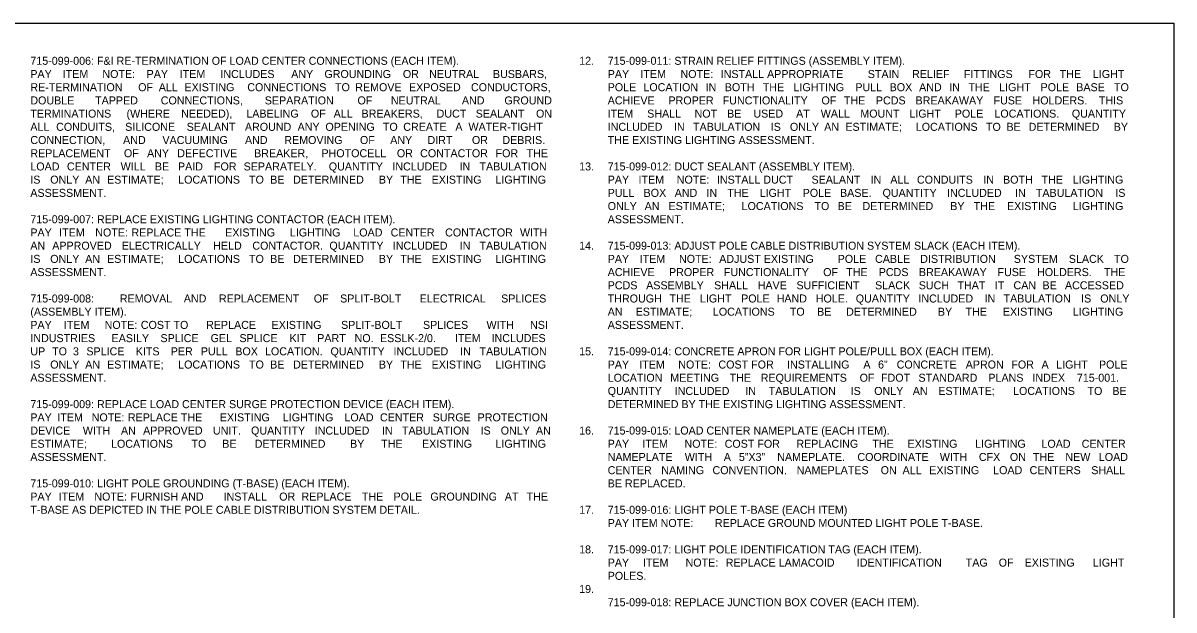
# Model space of a CAD drawing. Extents: x -55 to 2471539, y -90 to 3608906.
# Drawn here: x 543 to 1540, y 452 to 960 of the extents above; entities that cross this region are included whole.
import ezdxf

# ---------------------------------------------------------------- set-up
doc = ezdxf.new("R2010")
doc.units = 0
doc.layers.add('NonPlottingEle_dp', color=7, linetype='Continuous')
doc.layers.add('TextNotes', color=7, linetype='Continuous')

msp = doc.modelspace()

# ---------------------------------------------------------------- linework, layer by layer
at = {"layer": 'NonPlottingEle_dp'}
msp.add_lwpolyline([(0, 0), (0, 960), (1540, 960), (1540, 0)], dxfattribs=at)

# ---------------------------------------------------------------- texts
at = {"layer": 'TextNotes'}
for s, p in [('715-099-006: F&I RE-TERMINATION OF LOAD CENTER CONNECTIONS (EACH ITEM).', (549.7, 923.83)), ('12.', (1024.92, 923.83)), ('715-099-011: STRAIN RELIEF FITTINGS (ASSEMBLY ITEM).', (1049.65, 923.83)), ('PAY ', (549.7, 912.39)), ('ITEM ', (577.74, 912.39)), ('NOTE: ', (612.1, 912.39)), ('PAY ', (650.39, 912.39)), ('ITEM ', (679.08, 912.39)), ('INCLUDES ', (714.25, 912.39)), ('ANY ', (775.58, 912.39)), ('GROUNDING ', (804.34, 912.39)), ('OR ', (872.29, 912.39)), ('NEUTRAL ', (895.07, 912.39)), ('BUSBARS, ', (950.28, 912.39)), ('PAY ', (1049.65, 912.39)), ('ITEM ', (1077.96, 912.39)), ('NOTE:', (1112.68, 912.39)), (' INSTALL APPROPRIATE ', (1144.9, 912.39)), ('STAIN ', (1274.84, 912.39)), ('RELIEF ', (1313.22, 912.39)), ('FITTINGS ', (1358.13, 912.39)), ('FOR ', (1413.95, 912.39)), ('THE ', (1441.06, 912.39)), ('LIGHT ', (1469.78, 912.39)), ('RE-TERMINATION ', (549.7, 900.96)), ('OF ', (643.08, 900.96)), ('ALL ', (660.93, 900.96)), ('EXISTING ', (683.15, 900.96)), ('CONNECTIONS ', (737.56, 900.96)), ('TO ', (813.52, 900.96)), ('REMOVE ', (831.03, 900.96)), ('EXPOSED ', (877.57, 900.96)), ('CONDUCTORS, ', (931.26, 900.96)), ('POLE ', (1049.65, 900.96)), ('LOCATION ', (1080.56, 900.96)), ('IN ', (1134.43, 900.96)), ('BOTH ', (1151.04, 900.96)), ('THE ', (1183.91, 900.96)), ('LIGHTING ', (1210.53, 900.96)), ('PULL ', (1264.1, 900.96)), ('BOX ', (1293.78, 900.96)), ('AND ', (1319.3, 900.96)), ('IN ', (1345.38, 900.96)), ('THE ', (1361.99, 900.96)), ('LIGHT ', (1388.61, 900.96)), ('POLE ', (1424.48, 900.96)), ('BASE ', (1455.39, 900.96)), ('TO ', (1488.08, 900.96)), ('DOUBLE ', (549.7, 889.52)), ('TAPPED ', (605.77, 889.52)), ('CONNECTIONS, ', (662.65, 889.52)), ('SEPARATION ', (752.7, 889.52)), ('OF ', (833, 889.52)), ('NEUTRAL ', (861.91, 889.52)), ('AND ', (923.39, 889.52)), ('GROUND ', (960.17, 889.52)), ('ACHIEVE ', (1049.65, 889.52)), ('PROPER ', (1102.26, 889.52)), ('FUNCTIONALITY ', (1149.23, 889.52)), ('OF ', (1234.77, 889.52)), ('THE ', (1254.12, 889.52)), ('PCDS ', (1281.88, 889.52)), ('BREAKAWAY ', (1316.19, 889.52)), ('FUSE ', (1383.74, 889.52)), ('HOLDERS. ', (1417.5, 889.52)), ('THIS ', (1474.9, 889.52)), ('TERMINATIONS ', (549.7, 878.09)), ('(WHERE ', (633, 878.09)), ('NEEDED), ', (680.31, 878.09)), ('LABELING ', (736.72, 878.09)), ('OF ', (792.62, 878.09)), ('ALL ', (812.36, 878.09)), ('BREAKERS, ', (836.49, 878.09)), ('DUCT ', (901.5, 878.09)), ('SEALANT ', (935.34, 878.09)), ('ON ', (987.58, 878.09)), ('ITEM ', (1049.65, 878.09)), ('SHALL ', (1083.84, 878.09)), ('NOT ', (1124.85, 878.09)), ('BE ', (1153.02, 878.09)), ('USED ', (1175.78, 878.09)), ('AT ', (1212.78, 878.09)), ('WALL ', (1234.12, 878.09)), ('MOUNT ', (1268.41, 878.09)), ('LIGHT ', (1310.87, 878.09)), ('POLE ', (1350.18, 878.09)), ('LOCATIONS. ', (1384.52, 878.09)), ('QUANTITY ', (1451.55, 878.09)), ('ALL ', (549.7, 866.65)), ('CONDUITS, ', (572.05, 866.65)), ('SILICONE ', (631.83, 866.65)), ('SEALANT ', (685.05, 866.65)), ('AROUND ', (735.51, 866.65)), ('ANY ', (781.11, 866.65)), ('OPENING ', (805.22, 866.65)), ('TO ', (854.97, 866.65)), ('CREATE ', (872.61, 866.65)), ('A ', (917.72, 866.65)), ('WATER-TIGHT ', (929.09, 866.65)), ('INCLUDED ', (1049.65, 866.65)), ('IN ', (1107.05, 866.65)), ('TABULATION ', (1123.54, 866.65)), ('IS ', (1190.8, 866.65)), ('ONLY ', (1207.43, 866.65)), ('AN ', (1237.1, 866.65)), ('ESTIMATE; ', (1255.46, 866.65)), ('LOCATIONS ', (1316.43, 866.65)), ('TO ', (1377.19, 866.65)), ('BE ', (1394.94, 866.65)), ('DETERMINED ', (1414.15, 866.65)), ('BY ', (1487.82, 866.65)), ('CONNECTION, ', (549.7, 855.22)), ('AND ', (630.03, 855.22)), ('VACUUMING ', (664.09, 855.22)), ('AND ', (735.55, 855.22)), ('REMOVING ', (769.61, 855.22)), ('OF ', (835.13, 855.22)), ('ANY ', (861.32, 855.22)), ('DIRT ', (893.64, 855.22)), ('OR ', (932.08, 855.22)), ('DEBRIS. ', (958.43, 855.22)), ('THE EXISTING LIGHTING ASSESSMENT.', (1049.65, 855.22)), ('REPLACEMENT ', (549.7, 843.78)), ('OF ', (630.73, 843.78)), ('ANY ', (650.75, 843.78)), ('DEFECTIVE ', (676.9, 843.78)), ('BREAKER, ', (743.47, 843.78)), ('PHOTOCELL ', (801.75, 843.78)), ('OR ', (867.07, 843.78)), ('CONTACTOR ', (887.24, 843.78)), ('FOR ', (952.56, 843.78)), ('THE ', (979.39, 843.78)), ('LOAD ', (549.7, 832.35)), ('CENTER ', (581.37, 832.35)), ('WILL ', (627.9, 832.35)), ('BE ', (657.55, 832.35)), ('PAID ', (677.54, 832.35)), ('FOR ', (708.69, 832.35)), ('SEPARATELY. ', (734.37, 832.35)), ('QUANTITY ', (808.13, 832.35)), ('INCLUDED ', (863.18, 832.35)), ('IN ', (921.36, 832.35)), ('TABULATION ', (938.63, 832.35)), ('13.', (1024.92, 832.35)), ('715-099-012: DUCT SEALANT (ASSEMBLY ITEM).', (1049.65, 832.35)), ('IS ', (549.7, 820.92)), ('ONLY ', (566.92, 820.92)), ('AN ', (597.19, 820.92)), ('ESTIMATE; ', (616.14, 820.92)), ('LOCATIONS ', (677.71, 820.92)), ('TO ', (739.06, 820.92)), ('BE ', (757.41, 820.92)), ('DETERMINED ', (777.21, 820.92)), ('BY ', (851.47, 820.92)), ('THE ', (870.08, 820.92)), ('EXISTING ', (897.18, 820.92)), ('LIGHTING ', (952.43, 820.92)), ('PAY ', (1049.65, 820.92)), ('ITEM ', (1076.33, 820.92)), ('NOTE:', (1109.42, 820.92)), (' INSTALL DUCT ', (1141.64, 820.92)), ('SEALANT ', (1226.14, 820.92)), ('IN ', (1277.3, 820.92)), ('ALL ', (1294.38, 820.92)), ('CONDUITS ', (1317.44, 820.92)), ('IN ', (1374.88, 820.92)), ('BOTH ', (1391.96, 820.92)), ('THE ', (1425.29, 820.92)), ('LIGHTING ', (1452.38, 820.92)), ('ASSESSMENT.', (549.7, 809.48)), ('PULL ', (1049.65, 809.48)), ('BOX ', (1080.74, 809.48)), ('AND ', (1107.67, 809.48)), ('IN ', (1135.17, 809.48)), ('THE ', (1153.18, 809.48)), ('LIGHT ', (1181.21, 809.48)), ('POLE ', (1218.5, 809.48)), ('BASE. ', (1250.83, 809.48)), ('QUANTITY ', (1287.65, 809.48)), ('INCLUDED ', (1343.46, 809.48)), ('IN ', (1402.39, 809.48)), ('TABULATION ', (1420.41, 809.48)), ('IS ', (1489.2, 809.48)), ('ONLY ', (1049.65, 798.05)), ('AN ', (1081.64, 798.05)), ('ESTIMATE; ', (1102.31, 798.05)), ('LOCATIONS ', (1165.6, 798.05)), ('TO ', (1228.68, 798.05)), ('BE ', (1248.75, 798.05)), ('DETERMINED ', (1270.27, 798.05)), ('BY ', (1346.26, 798.05)), ('THE ', (1366.59, 798.05)), ('EXISTING ', (1395.4, 798.05)), ('LIGHTING ', (1452.38, 798.05)), ('715-099-007: REPLACE EXISTING LIGHTING CONTACTOR (EACH ITEM).', (549.7, 786.61)), ('ASSESSMENT.', (1049.65, 786.61)), ('PAY ', (549.7, 775.18)), ('ITEM ', (574.65, 775.18)), ('NOTE:', (605.91, 775.18)), (' REPLACE THE ', (634.66, 775.18)), ('EXISTING ', (718.38, 775.18)), ('LIGHTING ', (774.46, 775.18)), ('LOAD ', (829.35, 775.18)), ('CENTER ', (861.68, 775.18)), ('CONTACTOR ', (908.87, 775.18)), ('WITH ', (973.69, 775.18)), ('AN ', (549.7, 763.74)), ('APPROVED ', (568.66, 763.74)), ('ELECTRICALLY ', (628.89, 763.74)), ('HELD ', (708.04, 763.74)), ('CONTACTOR. ', (741.94, 763.74)), ('QUANTITY ', (808.65, 763.74)), ('INCLUDED ', (863.54, 763.74)), ('IN ', (921.54, 763.74)), ('TABULATION ', (938.63, 763.74)), ('14.', (1024.92, 763.74)), ('715-099-013: ADJUST POLE CABLE DISTRIBUTION SYSTEM SLACK (EACH ITEM).', (1049.65, 763.74)), ('IS ', (549.7, 752.31)), ('ONLY ', (566.92, 752.31)), ('AN ', (597.19, 752.31)), ('ESTIMATE; ', (616.14, 752.31)), ('LOCATIONS ', (677.71, 752.31)), ('TO ', (739.06, 752.31)), ('BE ', (757.41, 752.31)), ('DETERMINED ', (777.21, 752.31)), ('BY ', (851.47, 752.31)), ('THE ', (870.08, 752.31)), ('EXISTING ', (897.18, 752.31)), ('LIGHTING ', (952.43, 752.31)), ('PAY ', (1049.65, 752.31)), ('ITEM ', (1077.32, 752.31)), ('NOTE:', (1111.4, 752.31)), (' ADJUST EXISTING ', (1143.62, 752.31)), ('POLE ', (1248.79, 752.31)), ('CABLE ', (1281.16, 752.31)), ('DISTRIBUTION ', (1320.28, 752.31)), ('SYSTEM ', (1401.32, 752.31)), ('SLACK ', (1448.94, 752.31)), ('TO ', (1488.08, 752.31)), ('ASSESSMENT.', (549.7, 740.87)), ('ACHIEVE ', (1049.65, 740.87)), ('PROPER ', (1102.75, 740.87)), ('FUNCTIONALITY ', (1150.22, 740.87)), ('OF ', (1236.24, 740.87)), ('THE ', (1256.09, 740.87)), ('PCDS ', (1284.34, 740.87)), ('BREAKAWAY ', (1319.14, 740.87)), ('FUSE ', (1387.19, 740.87)), ('HOLDERS. ', (1421.44, 740.87)), ('THE ', (1479.34, 740.87)), ('PCDS ', (1049.65, 729.44)), ('ASSEMBLY ', (1082.95, 729.44)), ('SHALL ', (1141.8, 729.44)), ('HAVE ', (1179.52, 729.44)), ('SUFFICIENT ', (1213.08, 729.44)), ('SLACK ', (1281.14, 729.44)), ('SUCH ', (1318.96, 729.44)), ('THAT ', (1352.48, 729.44)), ('IT ', (1384.84, 729.44)), ('CAN ', (1401.03, 729.44)), ('BE ', (1426.14, 729.44)), ('ACCESSED ', (1445.6, 729.44)), ('715-099-008: ', (549.7, 718.01)), ('REMOVAL ', (627.22, 718.01)), ('AND ', (682.58, 718.01)), ('REPLACEMENT ', (713.02, 718.01)), ('OF ', (795.16, 718.01)), ('SPLIT-BOLT ', (817.95, 718.01)), ('ELECTRICAL ', (886.82, 718.01)), ('SPLICES ', (957.38, 718.01)), ('THROUGH ', (1049.65, 718.01)), ('THE ', (1103.1, 718.01)), ('LIGHT ', (1129.53, 718.01)), ('POLE ', (1165.21, 718.01)), ('HAND ', (1195.94, 718.01)), ('HOLE. ', (1229.82, 718.01)), ('QUANTITY ', (1264.46, 718.01)), ('INCLUDED ', (1318.67, 718.01)), ('IN ', (1376, 718.01)), ('TABULATION ', (1392.41, 718.01)), ('IS ', (1459.6, 718.01)), ('ONLY ', (1476.16, 718.01)), ('(ASSEMBLY ITEM).', (549.7, 706.57)), ('AN ', (1049.65, 706.57)), ('ESTIMATE; ', (1073.88, 706.57)), ('LOCATIONS ', (1140.72, 706.57)), ('TO ', (1207.35, 706.57)), ('BE ', (1230.98, 706.57)), ('DETERMINED ', (1256.05, 706.57)), ('BY ', (1335.59, 706.57)), ('THE ', (1359.48, 706.57)), ('EXISTING ', (1391.85, 706.57)), ('LIGHTING ', (1452.38, 706.57)), ('PAY ', (549.7, 695.14)), ('ITEM ', (578.71, 695.14)), ('NOTE:', (614.04, 695.14)), (' COST TO ', (642.79, 695.14)), ('REPLACE ', (701.88, 695.14)), ('EXISTING ', (758.59, 695.14)), ('SPLIT-BOLT ', (818.75, 695.14)), ('SPLICES ', (889.71, 695.14)), ('WITH ', (944.7, 695.14)), ('NSI ', (982.39, 695.14)), ('ASSESSMENT.', (1049.65, 695.14)), ('INDUSTRIES ', (549.7, 683.7)), ('EASILY ', (620.06, 683.7)), ('SPLICE ', (662.4, 683.7)), ('GEL ', (705.81, 683.7)), ('SPLICE ', (730.78, 683.7)), ('KIT ', (774.19, 683.7)), ('PART ', (798.14, 683.7)), ('NO. ', (830.48, 683.7)), ('ESSLK-2/0. ', (852.45, 683.7)), ('ITEM ', (917.5, 683.7)), ('INCLUDES ', (949.08, 683.7)), ('UP ', (549.7, 672.27)), ('TO ', (568.55, 672.27)), ('3 ', (586.58, 672.27)), ('SPLICE ', (598.22, 672.27)), ('KITS ', (640.97, 672.27)), ('PER ', (671.27, 672.27)), ('PULL ', (697.35, 672.27)), ('BOX ', (727.19, 672.27)), ('LOCATION. ', (752.87, 672.27)), ('QUANTITY ', (809.62, 672.27)), ('INCLUDED ', (864.18, 672.27)), ('IN ', (921.86, 672.27)), ('TABULATION ', (938.63, 672.27)), ('15.', (1024.92, 672.27)), ('715-099-014: CONCRETE APRON FOR LIGHT POLE/PULL BOX (EACH ITEM).', (1049.65, 672.27)), ('IS ', (549.7, 660.83)), ('ONLY ', (566.92, 660.83)), ('AN ', (597.19, 660.83)), ('ESTIMATE; ', (616.14, 660.83)), ('LOCATIONS ', (677.71, 660.83)), ('TO ', (739.06, 660.83)), ('BE ', (757.41, 660.83)), ('DETERMINED ', (777.21, 660.83)), ('BY ', (851.47, 660.83)), ('THE ', (870.08, 660.83)), ('EXISTING ', (897.18, 660.83)), ('LIGHTING ', (952.43, 660.83)), ('PAY ', (1049.65, 660.83)), ('ITEM ', (1076.99, 660.83)), ('NOTE:', (1110.74, 660.83)), (' COST FOR ', (1142.95, 660.83)), ('INSTALLING ', (1204.94, 660.83)), ('A ', (1271.03, 660.83)), ('6” ', (1283.76, 660.83)), ('CONCRETE ', (1299.86, 660.83)), ('APRON ', (1359.65, 660.83)), ('FOR ', (1399.16, 660.83)), ('A ', (1425.31, 660.83)), ('LIGHT ', (1438.04, 660.83)), ('POLE ', (1475.04, 660.83)), ('ASSESSMENT.', (549.7, 649.4)), ('LOCATION ', (1049.65, 649.4)), ('MEETING ', (1103.84, 649.4)), ('THE ', (1155.2, 649.4)), ('REQUIREMENTS ', (1182.14, 649.4)), ('OF ', (1267.79, 649.4)), ('FDOT ', (1286.32, 649.4)), ('STANDARD ', (1318.77, 649.4)), ('PLANS ', (1379.26, 649.4)), ('INDEX ', (1417.35, 649.4)), ('715-001. ', (1455.91, 649.4)), ('QUANTITY ', (1049.65, 637.96)), ('INCLUDED ', (1107.67, 637.96)), ('IN ', (1168.81, 637.96)), ('TABULATION ', (1189.04, 637.96)), ('IS ', (1260.04, 637.96)), ('ONLY ', (1280.41, 637.96)), ('AN ', (1313.83, 637.96)), ('ESTIMATE; ', (1335.92, 637.96)), ('LOCATIONS ', (1400.64, 637.96)), ('TO ', (1465.14, 637.96)), ('BE ', (1486.63, 637.96)), ('715-099-009: REPLACE LOAD CENTER SURGE PROTECTION DEVICE (EACH ITEM).', (549.7, 626.53)), ('DETERMINED BY THE EXISTING LIGHTING ASSESSMENT.', (1049.65, 626.53)), ('PAY ', (549.7, 615.09)), ('ITEM ', (573.11, 615.09)), ('NOTE:', (602.83, 615.09)), (' REPLACE THE ', (631.58, 615.09)), ('EXISTING ', (713.76, 615.09)), ('LIGHTING ', (768.31, 615.09)), ('LOAD ', (821.67, 615.09)), ('CENTER ', (852.46, 615.09)), ('SURGE ', (898.1, 615.09)), ('PROTECTION ', (937, 615.09)), ('DEVICE ', (549.7, 603.66)), ('WITH ', (595.15, 603.66)), ('AN ', (628.17, 603.66)), ('APPROVED ', (647.36, 603.66)), ('UNIT. ', (707.81, 603.66)), ('QUANTITY ', (740.82, 603.66)), ('INCLUDED ', (795.93, 603.66)), ('IN ', (854.16, 603.66)), ('TABULATION ', (871.48, 603.66)), ('IS ', (939.57, 603.66)), ('ONLY ', (957.03, 603.66)), ('AN ', (987.53, 603.66)), ('16.', (1024.92, 603.66)), ('715-099-015: LOAD CENTER NAMEPLATE (EACH ITEM).', (1049.65, 603.66)), ('ESTIMATE; ', (549.7, 592.23)), ('LOCATIONS ', (619.57, 592.23)), ('TO ', (689.23, 592.23)), ('BE ', (715.88, 592.23)), ('DETERMINED ', (743.99, 592.23)), ('BY ', (826.56, 592.23)), ('THE ', (853.47, 592.23)), ('EXISTING ', (888.87, 592.23)), ('LIGHTING ', (952.43, 592.23)), ('PAY ', (1049.65, 592.23)), ('ITEM ', (1079.69, 592.23)), ('NOTE:', (1116.13, 592.23)), (' COST FOR ', (1148.35, 592.23)), ('REPLACING ', (1213.03, 592.23)), ('THE ', (1278.81, 592.23)), ('EXISTING ', (1309.25, 592.23)), ('LIGHTING ', (1367.85, 592.23)), ('LOAD ', (1425.25, 592.23)), ('CENTER ', (1460.09, 592.23)), ('ASSESSMENT.', (549.7, 580.79)), ('NAMEPLATE ', (1049.65, 580.79)), ('WITH ', (1116.36, 580.79)), ('A ', (1150.17, 580.79)), ('5”X3” ', (1163.28, 580.79)), ('NAMEPLATE. ', (1196.44, 580.79)), ('COORDINATE ', (1265.87, 580.79)), ('WITH ', (1337.24, 580.79)), ('CFX ', (1371.06, 580.79)), ('ON ', (1397.91, 580.79)), ('THE ', (1417.85, 580.79)), ('NEW ', (1445.97, 580.79)), ('LOAD ', (1474.94, 580.79)), ('CENTER ', (1049.65, 569.36)), ('NAMING ', (1096.05, 569.36)), ('CONVENTION. ', (1140.41, 569.36)), ('NAMEPLATES ', (1213.26, 569.36)), ('ON ', (1286.01, 569.36)), ('ALL ', (1304.97, 569.36)), ('EXISTING ', (1328.1, 569.36)), ('LOAD ', (1383.41, 569.36)), ('CENTERS ', (1414.96, 569.36)), ('SHALL ', (1468.36, 569.36)), ('715-099-010: LIGHT POLE GROUNDING (T-BASE) (EACH ITEM).', (549.7, 557.92)), ('BE REPLACED.', (1049.65, 557.92)), ('PAY ', (549.7, 546.49)), ('ITEM ', (574.25, 546.49)), ('NOTE:', (605.11, 546.49)), (' FURNISH AND ', (633.86, 546.49)), ('INSTALL ', (717.03, 546.49)), ('OR ', (765.21, 546.49)), ('REPLACE ', (784.49, 546.49)), ('THE ', (836.74, 546.49)), ('POLE ', (864.27, 546.49)), ('GROUNDING ', (896.1, 546.49)), ('AT ', (960.55, 546.49)), ('THE ', (979.39, 546.49)), ('T-BASE AS DEPICTED IN THE POLE CABLE DISTRIBUTION SYSTEM DETAIL.', (549.7, 535.05)), ('17.', (1024.92, 535.05)), ('715-099-016: LIGHT POLE T-BASE (EACH ITEM)', (1049.65, 535.05)), ('PAY ITEM NOTE:', (1049.65, 523.62)), (' REPLACE GROUND MOUNTED LIGHT POLE T-BASE.', (1139.91, 523.62)), ('18.', (1024.92, 500.75)), ('715-099-017: LIGHT POLE IDENTIFICATION TAG (EACH ITEM).', (1049.65, 500.75)), ('PAY ', (1049.65, 489.32)), ('ITEM ', (1080.15, 489.32)), ('NOTE:', (1117.06, 489.32)), (' REPLACE LAMACOID ', (1149.28, 489.32)), ('IDENTIFICATION ', (1265.35, 489.32)), ('TAG ', (1359.67, 489.32)), ('OF ', (1388.22, 489.32)), ('EXISTING ', (1410.72, 489.32)), ('LIGHT ', (1469.78, 489.32)), ('POLES.', (1049.65, 477.88)), ('19.', (1024.92, 466.45)), ('715-099-018: REPLACE JUNCTION BOX COVER (EACH ITEM).', (1049.65, 455.01))]:
    msp.add_text(s, height=6.93, dxfattribs=at).set_placement(p)

doc.saveas('drawing.dxf')
